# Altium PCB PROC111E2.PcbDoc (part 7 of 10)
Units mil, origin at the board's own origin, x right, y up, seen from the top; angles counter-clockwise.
Board outline 7700 x 2300 mil, 6 copper layers (Top Layer, GND 1, SIG 1, SIG 2, GND 2, Bottom Layer), stack 78.711 mil thick; 767 components, 596 nets, 2755 pads, 1578 vias.
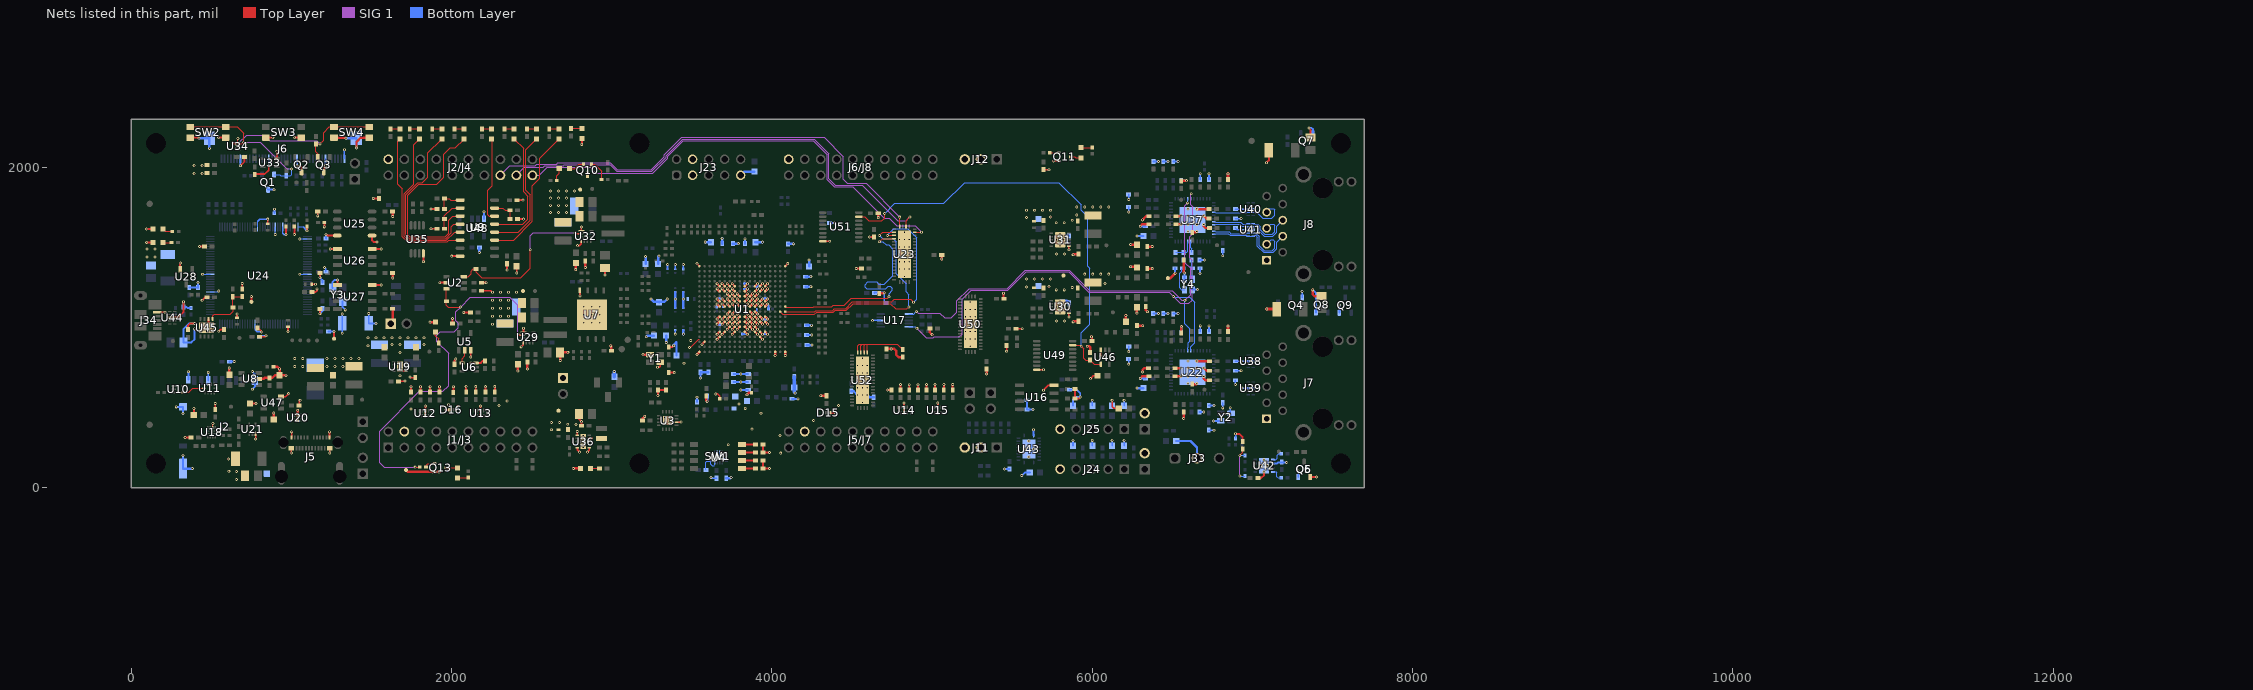
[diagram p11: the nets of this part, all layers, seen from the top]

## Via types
v1: diameter 18, hole 8, Top Layer to Bottom Layer, tented both sides, 1474 vias
v2: diameter 19.68, hole 7.87, Top Layer to Bottom Layer, tented both sides, 104 vias

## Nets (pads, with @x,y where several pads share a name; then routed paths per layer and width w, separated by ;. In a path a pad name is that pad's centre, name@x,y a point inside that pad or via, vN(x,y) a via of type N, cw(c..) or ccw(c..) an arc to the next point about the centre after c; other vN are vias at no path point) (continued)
ETH2_TD_B_P: J8.7 U37.4 U40.4 U40.7 | length 512.4
  Bottom Layer w4: U37.4@6759.03,1719.25 6766.12,1719.25 6770.11,1715.26 6951.17,1715.26 6961.96,1715.26 6965.96,1719.25 U40.7@6973.14,1719.25 U40.4@7006.02,1719.25 7013.2,1719.25 7017.19,1715.26 7031.41,1715.26 7065.94,1680.74 7120,1680.74 7140.49,1701.23 7140.49,1734.84 7132.92,1742.41 7101.74,1742.41 7089.08,1729.76 J8.7@7089.08,1720
ETH2_TD_C_N: J8.6 U37.8 U41.2 U41.9 | length 543.1
  Bottom Layer w4: U37.8@6759.03,1640.51 6766.12,1640.51 6770.11,1644.5 6922.46,1644.5 6933.69,1633.28 6961.69,1633.28 6965.69,1629.28 U41.9@6972.87,1629.28 U41.2@7005.75,1629.28 7012.93,1629.28 7016.92,1633.28 7030,1633.28 7038.3,1624.98 7038.3,1604.25 7073.24,1569.3 7127.85,1569.3 7152.19,1593.65 7152.19,1633.12 J8.6@7189.08,1670
ETH2_TD_C_P: J8.5 U37.7 U41.1 U41.10 | length 541.7
  Bottom Layer w4: U37.7@6759.03,1660.2 6766.12,1660.2 6770.11,1656.2 6927.31,1656.2 6938.54,1644.98 6961.69,1644.98 6965.69,1648.97 U41.10@6972.87,1648.97 U41.1@7005.75,1648.97 7012.93,1648.97 7016.92,1644.98 7034.85,1644.98 7050,1629.82 7050,1609.09 7078.09,1581 7123,1581 7140.49,1598.5 7140.49,1639.01 7134.5,1645 7114.08,1645 J8.5@7089.08,1620
ETH2_TD_D_N: J8.4 U37.11 U41.5 U41.6 | length 583.9
  Bottom Layer w4: U37.11@6759.03,1581.46 6766.12,1581.46 6770.11,1585.45 6850,1585.45 6861.23,1574.22 6961.69,1574.22 6965.69,1570.23 U41.6@6972.87,1570.23 U41.5@7005.75,1570.23 7012.93,1570.23 7016.92,1574.22 7020.52,1574.22 7031.57,1563.18 7031.57,1506.63 7070.15,1468.05 7129.73,1468.05 7152.19,1490.51 7152.19,1533.12 J8.4@7189.08,1570
ETH2_TD_D_P: J8.3 U37.10 U41.4 U41.7 | length 583.2
  Bottom Layer w4: U37.10@6759.03,1601.14 6766.12,1601.14 6770.11,1597.15 6854.85,1597.15 6866.07,1585.92 6961.69,1585.92 6965.69,1589.91 U41.7@6972.87,1589.91 U41.4@7005.75,1589.91 7012.93,1589.91 7016.92,1585.92 7025.37,1585.92 7043.27,1568.02 7043.27,1511.48 7075,1479.75 7124.88,1479.75 7140.49,1495.36 7140.49,1536.72 7129.83,1547.39 7116.46,1547.39 J8.3@7089.08,1520
ETH2_XI: R212.2 R213.2 U37.20 | length 139
  Bottom Layer w5.3: R213.2@6520,1468.62 R212.2@6570,1468.62 6588.54,1468.62 6595.65,1475.73 U37.20@6595.65,1536.18
ETH2_XO: R214.2 U37.19 | length 69.5
  Bottom Layer w5.3: U37.19@6615.33,1536.18 6615.33,1496.87 6620,1492.2 R214.2@6620,1468.62
ETH2_XTAL_XI: C189.1 R212.1 Y4.1 | length 219.5
  Bottom Layer w5.3: R212.1@6570,1421.38 6570,1375 C189.1@6565,1370 6557.39,1362.39 6557.39,1350 6545,1337.61 6545,1248.66 6557.24,1236.42 Y4.1@6576.38,1236.42
ETH2_XTAL_XO: C190.1 R214.1 Y4.3 | length 123.6
  Bottom Layer w5.3: R214.1@6620,1421.38 6620,1375 C190.1@6625,1370 6625,1301.78 Y4.3@6623.62,1300.4
FB_VDD_XDS3V3: C228.2 R251.1 R252.2 U45.5 | length 312.9
  Top Layer w5.3: U45.5@507.08,1053.44 507.08,1074.16 515.69,1082.78 617.61,1082.78 635.03,1100.19 C228.2@635.03,1124.76 631.97,1127.82 R251.1@631.97,1191.61 690.03,1191.61 R252.2@691.97,1193.54
GND: C1.2 C2.2 C3.2 C4.2 C5.2 C6.2 C7.2 C8.2 C9.2 C10.2 C11.2 C12.2 C13.2 C14.2 C15.2 C16.2 C17.2 C18.2 C19.1 C20.1 C21.1 C22.1 C23.2 C24.2 C25.2 C26.2 C27.2 C28.2 C29.1 C30.1 C31.1 C32.1 C33.2 C34.2 C35.2 C36.2 C37.2 C38.2 C39.1 C40.1 C41.1 C42.1 C43.1 C44.1 C45.1 C46.1 C47.1 C48.2 C49.2 C50.2 C51.2 C52.2 C53.2 C54.2 C55.2 C56.2 C57.1 C58.2 C59.2 C60.1 C61.1 C62.1 C63.2 C64.1 C65.1 C66.1 C67.2 C68.2 C69.2 C70.1 C71.1 C72.2 C73.2 C74.2 C75.2 C81.2 C82.2 C83.2 C84.2 C85.2 C86.2 C87.2 C88.2 C89.2 C90.2 C91.2 C92.2 C93.2 C94.2 C95.2 C96.2 C97.2 C98.2 C99.1 C100.1 C101.2 C102.2 C103.2 C104.2 C105.2 C106.2 C107.2 C108.2 C109.2 C110.2 C111.1 C112.2 C113.2 C114.2 C115.2 C116.2 C117.2 C118.2 C119.2 C120.2 C121.2 C122.2 C123.2 C124.2 C125.2 C126.2 C127.2 C128.2 C129.2 C130.2 C131.2 C132.2 C133.2 C136.1 C137.1 C138.1 C157.2 C158.2 C159.2 C160.2 C161.2 C162.2 C163.2 C164.2 C165.2 C166.2 C167.2 C168.2 C169.2 C170.2 C171.2 C172.2 C173.2 C174.2 C175.2 C176.2 C177.2 C178.2 C179.2 C180.2 C181.1 C182.1 C183.1 C184.1 C185.2 C186.2 C187.2 C188.2 C189.2 C190.2 C191.2 C192.2 C193.2 C194.2 C195.2 C196.2 C197.2 C198.2 C199.2 C200.2 C201.2 C202.2 C203.2 C204.2 C205.2 C206.2 C207.2 C208.2 C209.2 C210.2 C211.2 C212.2 C213.2 C214.2 C215.2 C216.2 C217.2 C218.2 C219.2 C220.2 C221.2 C222.2 C223.1 C224.2 C225.1 C226.1 C229.1 C234.2 C235.1 C236.2 C237.2 C238.1 C239.1 C240.1 C241.1 C242.1 C243.1 C244.1 C245.1 C246.1 C247.1 C248.2 C249.2 D1.1 D2.1 D4.1 D6.1 D15.1 D16.2 J1/J3.22 J2.6 J2.10 J2.S1 J2.S2 J2.S3 J2.S4 J2/J4.20 J5.A1 J5.A12 J5.B1 J5.B12 J5/J7.62 J6.7 J6.16 J6.25 J6.34 J6.40 J6.41 J6.42 J6/J8.60 J7.1 J8.1 J11.2 J11.3 J12.2 J12.3 J15.2 J16.2 J17.1 J18.1 J23.3 J23.4 J23.9 J24.5 J25.5 J33.2 Q1.3 Q2.3 Q3.3 Q4.2 Q5.2 Q6.2 Q7.2 Q8.2 Q9.2 Q10.3 Q11.2 Q13.2 R2.1 R6.1 R20.2 R21.1 R22.1 R23.1 R24.1 R25.1 R32.2 R39.1 R44.1 R95.1 R96.1 R97.1 R98.2 R107.1 R120.1 R121.1 R122.1 R123.1 R124.1 R125.1 R126.1 R127.1 R128.1 R148.1 R152.1 R154.1 R160.1 R161.1 R163.1 R202.1 R215.1 R216.1 R217.1 R218.1 R219.1 R220.1 R221.1 R222.1 R223.1 R250.1 R254.2 R255.2 R256.1 R274.1 R275.1 R276.1 R278.1 R289.1 R290.1 R293.1 R294.1 R299.2 R300.1 R304.1 R307.1 R316.2 R321.1 R322.1 R323.1 SW2.1 SW2.3 SW3.1 SW3.3 SW4.1 SW4.3 TP6.1 TP13.1 TP14.1 TP15.1 TP16.1 TP17.1 U1.A1 U1.A18 U1.E5 U1.E6 U1.E7 U1.E8 U1.E10 U1.E12 U1.E13 U1.E14 U1.F5 U1.F6 U1.F7 U1.F8 U1.F10 U1.F12 U1.F13 U1.F14 U1.G7 U1.G8 U1.G9 U1.G10 U1.G11 U1.G12 U1.H5 U1.H6 U1.H7 U1.H8 U1.H9 U1.H10 U1.H11 U1.H12 U1.H13 U1.H14 U1.J5 U1.J6 U1.J7 U1.J8 U1.J9 U1.J10 U1.J11 U1.J12 U1.J13 U1.J14 U1.K7 U1.K8 U1.K9 U1.K10 U1.K11 U1.K12 U1.L5 U1.L6 U1.L7 U1.L8 U1.L9 U1.L10 U1.L11 U1.L12 U1.L13 U1.L14 U1.M5 U1.M6 U1.M7 U1.M8 U1.M9 U1.M10 U1.M11 U1.M12 U1.M13 U1.M14 U1.N7 U1.N8 U1.N9 U1.N10 U1.N11 U1.N12 U1.P5 U1.P6 U1.P8 U1.P10 U1.P12 U1.P13 U1.P14 U1.R5 U1.R13 U1.T2 U1.V1 U1.V16 U1.V18 U2.2 U3.6 U3.17@3348.05,418.7 U4.10 U4.11 U5.3 U6.3 U7.4 U7.9 U8.2 U9.3 U12.3@1835,448.04 U12.8@1835,480.91 U13.3@2180,448.56 U13.8@2180,481.44 U14.3@4825,467.68 U14.8@4825,500.55 U15.3@5035.4,467.82 U15.8@5035.4,500.69 U16.4 U17.3 U18.10 U19.5 U19.9 U20.3@1038.54,453.43 U20.8@1038.54,420.56 U21.3 U22.49 U23.43 U25.5 U26.4 U27.4 U29.4 U29.7 U30.6 U30.11 U31.6 U31.11 U32.4 U32.7 U33.3 U34.2 U35.4 U36.1 U36.5 U36.6 U36.11@2821.22,287.66 U37.49 U38.3@7006.02,788.94 U38.8@6973.14,788.94 U39.3@7005.75,619.6 U39.8@6972.87,619.6 U40.3@7006.02,1738.94 U40.8@6973.14,1738.94 U41.3@7005.75,1609.6 U41.8@6972.87,1609.6 U42.2 U42.9 U43.11 U43.21 U46.3 U47.3 U48.16 U49.8 U50.43 U51.8 U52.43 Y1.2 Y1.4 Y2.2 Y2.4 Y4.2 Y4.4 | length 17319.2
  Top Layer w5.3: v1@3483.94,875.56 3492.6,875.56 3532.61,915.57 3532.61,916.37 3541.12,924.88 3544.78,924.88
  Top Layer w6: U34.2@665,2146.97 v1@665,2179.53
  Top Layer w7: U18.10@508.07,374.61 v1(508.07,400)
  Top Layer w8: v1(664.53,2180) v1@665,2179.53 ; v1@1000.24,347.64 v1(1000.43,347.83) ; v1@1236.46,347.64 v1(1236.65,347.83) ; U3.6@3403.17,408.86 v1(3432.52,408.86)
  Top Layer w10: v1(680,2009.61) 705.62,2035.22 C181.1@705.62,2065 ; C182.1@769.3,1958.19 832.83,1958.19 857.17,1982.52 v1(857.17,2009.61) ; v1(775,302.93) U21.3@774.98,335.87 ; U47.3@933.63,568.4 963.4,568.4 v1(981.5,586.5) ; v1(998.27,216.05) J5.B12@998.27,245.67 ; R299.2@1047.12,512.5 1047.12,538.62 v1(1053.5,545) ; v1(1238.42,216.05) J5.B1@1238.42,245.67 ; R98.2@1668.62,663.27 1703.78,663.27 1705.51,665 v1(1707.67,665) ; U19.9@1676.92,755.91 1676.92,742.13 1689.64,729.41 1699.16,729.41 1700.3,728.27 1707.67,728.27 1709.56,726.38 U19.5@1714.33,726.38 ; v1(1740,690.32) 1743.94,686.38 C109.2@1771.58,686.38 ; v1(2433.37,878.82) 2446.36,891.81 U29.7@2446.36,905.26 ; U29.4@2448.33,971.21 v1(2448.33,995.01) ; v1(2785.5,1511) 2797,1511 2808.03,1522.03 U32.7@2808.03,1537.88 ; U32.4@2810,1603.83 v1(2810,1627.63) ; v1(3531.39,1398.54) U1.A1@3547.13,1382.8 ; v1(3648.81,585) 3661.54,585 3674.25,572.29 R307.1@3674.25,555 ; U1.A18@4082.57,1382.8 v1(4098.31,1398.54) ; U51.8@4317.8,1538.35 v1(4360.59,1538.35) ; v1(5465.31,851.27) R289.1@5465.31,887.92 ; U49.8@5652.8,735.66 v1(5695.59,735.66) ; v1(5854.25,1065.8) U30.6@5854.25,1089.06 ; v1(5854.25,1484.99) U31.6@5854.25,1508.25 ; v1(6124.18,545) 6124.18,504.64 6134.15,494.67 C221.2@6165.63,494.67
  Top Layer w11: J5.A1@1000.24,312.6 v1@1000.24,347.64 ; J5.A12@1236.46,312.6 v1@1236.46,347.64
  Top Layer w12: v1(335,312.6) R95.1@372.78,312.6 ; SW2.1@367.32,2185.35 417,2185.35 420.21,2182.15 v1(421.83,2182.15) ; C101.2@389.29,454.11 v1(389.29,493.25) ; R97.1@523.29,487.03 v1(523.29,525) ; v1(544.55,2185.35) SW2.3@587.8,2185.35 ; C110.2@740,525.04 v1(777.78,525.04) ; SW3.1@839.76,2185.35 v1(883.01,2185.35) ; U33.3@907.66,2053.74 v1(907.66,2100) ; v1(1016.99,2185.35) SW3.3@1060.24,2185.35 ; v1(1034.33,2009.61) 1055,2009.61 1062.25,2002.35 Q2.3@1062.25,1969.78 ; Q3.3@1201.12,1969.78 1201.14,1999.25 v1(1211.5,2009.61) ; U25.5@1502.36,1573.86 1502.36,1543.52 1512.61,1533.27 v1(1533.19,1533.27) ; U27.4@1503.27,1265.27 v1(1560,1265.27) ; U26.4@1503.27,1490 v1(1560,1490) ; v1(1510,1806) R21.1@1545,1806 ; C72.2@1745,595.57 v1(1745,629.98) ; C73.2@1805,595.57 v1(1805,629.98) ; v1(1822.76,1410.12) U35.4@1822.76,1462.4 ; U12.3@1835,448.04 U12.8@1835,480.91 v1(1835,509.48) ; C74.2@1865,595.57 v1(1865,629.98) ; v1(1870,1616.57) R276.1@1907.31,1616.57 ; v1(1870,1739.85) R274.1@1907.31,1739.85 ; C75.2@1924,595.57 v1(1924,629.98) ; v1(1925,1279.45) U2.2@1967.11,1279.45 ; v1(1960,485.1) D16.2@1984.92,485.1 ; v1(2000.43,1445) U48.16@2052.72,1445 ; C97.2@2010,595 v1(2010,629.41) ; C64.1@2017.57,770.1 2017.57,795.11 v1(2025,802.54) ; v1(2075.37,1094.07) R20.2@2117.18,1094.07 ; C81.2@2090,596.09 v1(2090,630.5) ; v1(2118.71,815.97) U5.3@2118.71,857.27 ; v1(2120.87,777.98) U6.3@2152.96,777.98 2179.73,777.98 2191.61,789.85 2207.84,789.85 C63.2@2207.84,791.01 ; C82.2@2150,596.09 v1(2150,630.5) ; U13.3@2180,448.56 U13.8@2180,481.44 v1(2180,510) ; C57.1@2186.02,1279.45 v1(2215,1279.45) ; R6.1@2186.34,1229.13 2244.97,1229.13 2254.1,1220 v1(2255,1220) ; C83.2@2210,596.09 v1(2210,630.5) ; C84.2@2269,596.09 v1(2269,630.5) ; v1(2345.94,1358.33) C237.2@2345.94,1397.76 ; v1(2405.95,1339.91) C236.2@2405.95,1382.01 ; R278.1@2408.62,1795 v1(2445.32,1795) ; R275.1@2411.63,1676.55 v1(2448.33,1676.55) ; v1(2759.42,119.25) v1@2759.91,119.75 ; U36.5@2783.82,248.29 2784.2,248.29 2784.2,235.76 v1(2798.5,221.46) ; U36.1@2783.82,327.03 v1(2783.82,350) ; C185.2@2795,458.99 2795,426.59 v1(2810,411.59) 2810.69,410.9 2810.69,386.65 C186.2@2811.38,385.96 ; U7.4@2800,1232.08 2800,1197.93 v1(2800.41,1197.52) ; v1(2812.21,2143.35) 2812.72,2143.87 D4.1@2812.72,2180.75 ; Q10.3@2848,1943.6 v1(2848,1974.32) ; v1(2848.5,221.46) 2858.62,231.57 U36.6@2858.62,248.29 ; R160.1@2956.47,1370.85 2956.47,1328.5 v1(2956.79,1328.18) ; v1(3285,751.21) 3294.48,751.21 3301.99,758.72 Y1.2@3301.99,782.59 ; v1(3287.35,575.17) 3287.47,575.29 C48.2@3287.47,609.62 R2.1@3337.66,609.62 ; C58.2@3355,717.59 3389.33,717.59 v1(3389.46,717.47) ; R23.1@3943.62,169.51 R22.1@3943.62,119.51 v1(3984.6,119.51) ; R25.1@3943.62,269.51 R24.1@3943.62,219.51 v1(3984.6,219.51) ; D15.1@4364.37,466.66 v1(4395.17,466.66) ; v1(4526.3,1367.86) 4526.37,1367.93 R290.1@4558.11,1367.93 ; v1(4720.59,608.97) 4720.69,608.87 4747.01,608.87 C85.2@4747.11,608.78 ; C86.2@4802.11,607.56 v1@4802.11,641.97 ; C86.2@4802.11,608.78 v1(4802.11,643.18) ; U14.3@4825,467.68 U14.8@4825,500.55 v1(4825,527.91) ; C87.2@4857.11,607.56 v1(4857.11,641.97) ; C88.2@4911.11,607.56 v1(4911.11,641.97) ; C92.2@4965,609.62 v1(4965,644.03) ; C93.2@5017.97,608.92 v1(5017.97,643.32) ; v1(5035,527.91) 5035.4,527.5 U15.8@5035.4,500.69 U15.3@5035.4,467.82 ; C94.2@5073,608.92 v1(5073,643.32) ; C95.2@5128.54,608.92 v1(5128.54,643.32) ; v1@5339.88,709.09 v1(5340,708.97) ; R294.1@5525,992.02 5562.09,992.02 v1(5562.51,991.6) ; v1(5694.94,607.56) 5726.52,639.14 U16.4@5760.08,639.14 ; R304.1@5695.31,1985.02 v1(5730,1985) ; v1(5756.81,2039.68) Q11.2@5790.6,2039.68 ; R323.1@5892.56,615 R321.1@5892.56,556.99 5916.9,556.99 v1(5924.91,565) ; v1(5989.5,680.45) 6007.43,698.38 C248.2@6032.6,698.38 ; v1(6054.41,820.59) U46.3@6054.41,859.29 ; v1(6895,335.87) 6919.4,335.87 6940,315.27 C222.2@6940,288.62 ; C226.1@7033.62,60.4 7055.4,60.4 7072.8,77.8 v2(7072.8,99.05) ; v1(7087.71,2028.68) 7102.48,2043.44 C247.1@7102.48,2106.97 ; v1(7354.16,2245) 7364.16,2234.97 R255.2@7364.16,2186.97 ; Q5.2@7361.4,66.42 v1(7400,66.42)
  Top Layer w13: U1.P12@3893.59,973.35 v1(3909.34,957.6) ; U1.P13@3925.09,973.35 v1(3940.83,957.6) ; U1.P14@3956.58,973.35 v1(3972.33,957.6)
  Top Layer w15: v1(610.92,746.73) 611.03,746.63 C67.2@611.03,704.19 ; U8.2@795.16,678.6 823.99,678.6 830.8,685.41 C69.2@862.1,685.41 880.37,685.41 896.06,701.1 924.7,701.1 C68.2@924.76,701.16 ; R39.1@886.92,754.8 911.3,754.8 924.76,741.35 C68.2@924.76,701.16 ; C249.2@888.36,425.41 v1(888.36,465.6) ; v1(965,701.1) 964.95,701.16 C68.2@924.76,701.16 ; U20.8@1038.54,420.56 U20.3@1038.54,453.43 v1(1038.54,483.13) ; SW4.1@1264.76,2185.35 1335.13,2185.35 1339.19,2181.3 v1(1340,2181.3) ; v1(1405,2120.99) 1405,2158.4 1431.95,2185.35 SW4.3@1485.24,2185.35 ; J17.1@1618.62,1023.77 1631.5,1036.64 C136.1@1631.5,1117.23 ; v1(1631.5,1308.81) C137.1@1631.5,1340 ; v1(1631.5,1692.68) C138.1@1631.5,1723.86 ; TP13.1@1715,110 1727.2,97.8 Q13.2@1892.6,97.8 v1(1921.18,97.8) ; v1(1864.39,1033.2) D2.1@1898.27,1033.2 ; v1(2004.54,1055.56) 2004.54,1025.93 C65.1@2005.6,1024.86 ; C160.2@2412.84,770.19 2412.84,728.44 v1(2413.01,728.27) ; R154.1@2472.33,783.06 2472.33,741.32 v1(2472.51,741.14) ; v1(2677.33,794.21) R148.1@2677.33,844.68 2724.68,844.68 v1(2725,845) ; v1@2759.91,119.75 D6.1@2803.5,119.75 ; C177.2@2774.51,1402.8 2774.51,1361.06 v1(2774.69,1360.89) ; R163.1@2834,1415.68 2834,1373.93 v1(2834.18,1373.76) ; v1(2993.31,885.26) 2997.24,881.32 C66.1@2997.24,854.15 ; C60.1@3191.38,418.33 3191.38,431.06 v1(3205.32,445) ; v1(3195,830) 3195.16,829.84 Y1.4@3238.01,829.84 ; C59.2@3355,877.96 3377.36,877.96 3385.25,885.85 v1(3386.07,885.85) ; v1(3531.39,831.61) U1.V1@3547.13,847.36 ; v1(3562.88,894.61) U1.T2@3578.63,910.35 ; C91.2@3590,571.38 3590,543.54 v1(3595,538.54) ; v1(3657.37,926.1) U1.R5@3673.12,941.85 ; v1(3657.37,957.6) U1.P5@3673.12,973.35 ; v1(3657.37,1020.59) U1.M5@3673.12,1036.34 ; v1(3657.37,1052.09) U1.L5@3673.12,1067.83 ; v1(3657.37,1146.57) U1.J5@3673.12,1130.83 ; v1(3657.37,1178.07) U1.H5@3673.12,1162.32 ; v1(3657.37,1241.06) U1.F5@3673.12,1225.32 ; v1(3657.37,1272.56) U1.E5@3673.12,1256.81 ; v1(3688.87,957.6) U1.P6@3704.61,973.35 ; v1(3688.87,1020.59) U1.M6@3704.61,1036.34 ; v1(3688.87,1052.09) U1.L6@3704.61,1067.83 ; v1(3688.87,1146.57) U1.J6@3704.61,1130.83 ; v1(3688.87,1178.07) U1.H6@3704.61,1162.32 ; v1(3688.87,1241.06) U1.F6@3704.61,1225.32 ; v1(3688.87,1272.56) U1.E6@3704.61,1256.81 ; v1(3720.36,989.09) U1.N7@3736.11,1004.84 ; v1(3720.36,1020.59) U1.M7@3736.11,1036.34 ; v1(3720.36,1052.09) U1.L7@3736.11,1067.83 ; v1(3720.36,1083.58) U1.K7@3736.11,1099.33 ; v1(3720.36,1146.57) U1.J7@3736.11,1130.83 ; v1(3720.36,1178.07) U1.H7@3736.11,1162.32 ; v1(3720.36,1209.57) U1.G7@3736.11,1193.82 ; v1(3720.36,1241.06) U1.F7@3736.11,1225.32 ; v1(3720.36,1272.56) U1.E7@3736.11,1256.81 ; v1(3751.86,957.6) U1.P8@3767.61,973.35 ; v1(3751.86,989.09) U1.N8@3767.61,1004.84 ; v1(3751.86,1020.59) U1.M8@3767.61,1036.34 ; v1(3751.86,1052.09) U1.L8@3767.61,1067.83 ; v1(3751.86,1083.58) U1.K8@3767.61,1099.33 ; v1(3751.86,1146.57) U1.J8@3767.61,1130.83 ; v1(3751.86,1178.07) U1.H8@3767.61,1162.32 ; v1(3751.86,1209.57) U1.G8@3767.61,1193.82 ; v1(3751.86,1241.06) U1.F8@3767.61,1225.32 ; v1(3751.86,1272.56) U1.E8@3767.61,1256.81 ; v1(3783.35,989.09) U1.N9@3799.1,1004.84 ; v1(3783.35,1020.59) U1.M9@3799.1,1036.34 ; v1(3783.35,1052.09) U1.L9@3799.1,1067.83 ; v1(3783.35,1083.58) U1.K9@3799.1,1099.33 ; v1(3783.35,1146.57) U1.J9@3799.1,1130.83 ; v1(3783.35,1178.07) U1.H9@3799.1,1162.32 ; v1(3783.35,1209.57) U1.G9@3799.1,1193.82 ; U1.P10@3830.6,973.35 v1(3846.35,957.6) ; U1.N10@3830.6,1004.84 v1(3846.35,989.09) ; U1.M10@3830.6,1036.34 v1(3846.35,1020.59) ; U1.L10@3830.6,1067.83 v1(3846.35,1052.09) ; U1.K10@3830.6,1099.33 v1(3846.35,1083.58) ; U1.J10@3830.6,1130.83 v1(3846.35,1146.57) ; U1.H10@3830.6,1162.32 v1(3846.35,1178.07) ; U1.G10@3830.6,1193.82 v1(3846.35,1209.57) ; U1.F10@3830.6,1225.32 v1(3846.35,1241.06) ; U1.E10@3830.6,1256.81 v1(3846.35,1272.56) ; v1(3843.32,579.5) 3855.66,591.83 R44.1@3872.63,591.83 ; U1.N11@3862.09,1004.84 v1(3877.84,989.09) ; U1.M11@3862.09,1036.34 v1(3877.84,1020.59) ; U1.L11@3862.09,1067.83 v1(3877.84,1052.09) ; U1.K11@3862.09,1099.33 v1(3877.84,1083.58) ; U1.J11@3862.09,1130.83 v1(3877.84,1146.57) ; U1.H11@3862.09,1162.32 v1(3877.84,1178.07) ; U1.G11@3862.09,1193.82 v1(3877.84,1209.57) ; U1.N12@3893.59,1004.84 v1(3909.34,989.09) ; U1.M12@3893.59,1036.34 v1(3909.34,1020.59) ; U1.L12@3893.59,1067.83 v1(3909.34,1052.09) ; U1.K12@3893.59,1099.33 v1(3909.34,1083.58) ; U1.J12@3893.59,1130.83 v1(3909.34,1146.57) ; U1.H12@3893.59,1162.32 v1(3909.34,1178.07) ; U1.G12@3893.59,1193.82 v1(3909.34,1209.57) ; U1.F12@3893.59,1225.32 v1(3909.34,1241.06) ; U1.E12@3893.59,1256.81 v1(3909.34,1272.56) ; U1.R13@3925.09,941.85 v1(3940.83,926.1) ; U1.M13@3925.09,1036.34 v1(3940.83,1020.59) ; U1.L13@3925.09,1067.83 v1(3940.83,1052.09) ; U1.J13@3925.09,1130.83 v1(3940.83,1146.57) ; U1.H13@3925.09,1162.32 v1(3940.83,1178.07) ; U1.F13@3925.09,1225.32 v1(3940.83,1241.06) ; U1.E13@3925.09,1256.81 v1(3940.83,1272.56) ; U1.M14@3956.58,1036.34 v1(3972.33,1020.59) ; U1.L14@3956.58,1067.83 v1(3972.33,1052.09) ; U1.J14@3956.58,1130.83 v1(3972.33,1146.57) ; U1.H14@3956.58,1162.32 v1(3972.33,1178.07) ; U1.F14@3956.58,1225.32 v1(3972.33,1241.06) ; U1.E14@3956.58,1256.81 v1(3972.33,1272.56) ; v1(4019.57,825) U1.V16@4019.57,847.36 ; v1(4082.57,825) U1.V18@4082.57,847.36 ; v1(4305.32,573.56) C96.2@4339.72,573.56 ; v1(4610,1564.77) C241.1@4636.65,1564.77 ; v1(4663.62,1685.42) C246.1@4663.62,1712.48 ; C240.1@4670.38,1213.22 4697.36,1213.22 v1(4701.07,1216.93) ; C245.1@4715,864.8 4716.1,865.9 v1(4745,865.9) 4763.67,865.9 4776.02,853.55 4776.02,828.46 4790.08,814.4 R256.1@4816.77,814.4 ; C111.1@4985.38,992.82 4985.38,969.7 v1(5000,955.08) ; v1(5060,1426.95) C242.1@5060,1451.95 ; v1@5339.88,709.09 C239.1@5339.88,741.15 ; C238.1@5445.86,1179.87 v1(5445.86,1213.79) ; v1(5880.69,1035) 5881.5,1035 5885.23,1038.74 R152.1@5914.13,1038.74 ; v1(5880.69,1454.19) 5881.5,1454.19 5885.23,1457.92 R161.1@5914.13,1457.92 ; v1(5968.5,882.8) 5981.65,882.8 5986.5,877.96 R96.1@5986.5,843.62 ; v1(5994.69,941.85) 5998.62,937.91 C43.1@5998.62,914.8 ; C122.2@6210,1035.15 v1(6210,1075.06) ; v1(6240,1379.35) 6240.74,1378.61 C114.2@6279,1378.61 ; v1(6240,1517.45) 6240.74,1516.71 C191.2@6279,1516.71 ; v1(6278.93,1089.06) C199.2@6278.93,1125.48 ; C123.2@6280.09,1010.77 v1(6315,1010.77) ; v1(6300,682.33) 6312.71,695.04 C133.2@6355.51,695.04 ; v1(6300,1632.33) 6312.71,1645.04 C210.2@6355.51,1645.04 ; v1(6313.62,721.81) 6313.62,735 6323.66,745.04 C119.2@6350.51,745.04 ; v1(6313.62,1671.81) 6336.85,1695.04 C196.2@6355.51,1695.04 ; C200.2@6334,1131.36 6334,1108.26 v1(6344,1098.26) ; C115.2@6344,1366.9 6374.83,1366.9 v1(6375,1367.07) ; C192.2@6344,1505 6374.83,1505 v1(6375,1505.17) ; TP16.1@6471.65,1308.13 6488.28,1308.13 v1(6517.76,1337.61) ; C132.2@6517.56,695.04 6551.07,695.04 6553.04,693.07 v2(6554.31,693.07) ; C118.2@6517.56,745.04 6552.34,745.04 v2(6554.31,747.01) ; C209.2@6522.56,1645.04 6552.34,1645.04 v2(6554.31,1643.07) ; C195.2@6522.56,1695.04 6552.34,1695.04 v2(6554.31,1697.01) ; C116.2@6556.28,968.7 v1(6556.28,1005) ; C193.2@6556.28,1915.34 6586.92,1915.34 v1(6588.38,1916.8) ; v1(6570.85,431.38) R126.1@6570.85,471.38 ; R221.1@6570.97,1421.26 6570.97,1343.94 v1(6575,1339.91) ; C130.2@6625,644.09 6647.07,644.09 v2(6652.14,649.17) ; C207.2@6625,1594.09 6647.07,1594.09 v2(6652.14,1599.17) ; v2(6652.14,790.91) 6654.11,788.94 C126.2@6731.79,788.94 ; v2(6652.14,1740.91) 6654.11,1738.94 C203.2@6727.79,1738.94 ; v2(6696.04,693.07) 6696.04,680.77 6705.98,670.83 C124.2@6731.79,670.83 ; v2(6696.04,747.01) 6713.17,729.88 C120.2@6731.79,729.88 ; v2(6696.04,1643.07) 6696.04,1630.77 6705.98,1620.83 C201.2@6731.79,1620.83 ; v2(6696.04,1697.01) 6713.17,1679.88 C197.2@6727.79,1679.88 ; v1(7377.27,1235) 7377.27,1206.56 7388.83,1195 R254.2@7430.57,1195
  Top Layer w20: R123.1@6848,973.31 v1(6848,1009.61) ; R218.1@6848,1923.31 v1(6848,1959.61) ; v1(7090,1115) C235.1@7152.32,1115
  Bottom Layer w7: v1@3658.2,198.58 U4.10@3658.2,219.28 ; 3673.95,202.09 U4.11@3673.95,219.28
  Bottom Layer w8: v1@3658.2,198.58 v1@3664.32,192.46 ; v1(3664.32,192.41) v1@3664.32,192.46 ; 3673.95,202.09 v1@3664.32,192.46 ; v1(4627.36,1042.24) 4628.87,1043.75 U17.3@4680.08,1043.75 ; R250.1@6895,307.24 v1(6895,335.87) ; v1(6930,1609.6) U41.8@6972.87,1609.6 U41.3@7005.75,1609.6
  Bottom Layer w10: J6.7@679.88,2053.35 679.88,2009.73 v1(680,2009.61) ; J6.16@857.05,2053.35 857.05,2009.73 v1(857.17,2009.61) ; J6.25@1034.21,2053.35 1034.21,2009.73 v1(1034.33,2009.61) ; J6.34@1211.38,2053.35 1211.38,2009.73 v1(1211.5,2009.61) ; J6.40@1329.49,2053.35 1329.49,2109.49 v1(1330,2110) ; C211.2@5880,261.5 v1(5880,295) ; C216.2@6000,261.5 v1(6000,295) ; C219.2@6000,511.5 v1(6000,545) ; C215.2@6124.18,261.5 v1(6124.18,295) ; C218.2@6124.18,511.5 v1(6124.18,545) ; C214.2@6199.18,261.5 v1(6199.18,295) ; C217.2@6199.18,511.5 v1(6199.18,545) ; v1(6893.84,643.12) C125.2@6893.84,670.83 ; C121.2@6893.84,729.88 v1(6930,729.88) ; C127.2@6893.84,788.94 v1(6930,788.94) U38.8@6973.14,788.94 U38.3@7006.02,788.94 ; C202.2@6893.84,1620.83 6905.06,1609.6 v1(6930,1609.6) ; C198.2@6893.84,1679.88 v1(6930,1679.88) ; C204.2@6893.84,1738.94 v1(6930,1738.94) U40.8@6973.14,1738.94 U40.3@7006.02,1738.94 ; v1(6935,621.55) 6937.16,621.55 6939.12,619.6 U39.8@6972.87,619.6 U39.3@7005.75,619.6
  Bottom Layer w12: v1(279.76,504.25) J2.S2@321.97,504.25 v1(321.97,462.05) ; J2.10@355.43,673.54 v1(355.43,723.39) ; J2.6@479.45,669.61 v1(479.45,719.45) ; C71.1@611.42,785.43 612.83,786.84 v1(641.79,786.84) ; v1(755,614.21) 770.79,630 J2.S1@770.79,669.61 770.79,709.21 v1(755,725) ; Q1.3@852.98,1860.51 889.49,1860.51 v1(890,1860) ; v1(1481.54,1086.51) C234.2@1481.54,1025 v1(1527.39,1025) ; U9.3@2201.37,1678.43 v1@2201.37,1722.46 ; C42.1@3348.24,1365.28 v1(3348.24,1393.66) ; v1(3395.84,958.19) C45.1@3395.84,981.57 ; C21.1@3395.84,1365.28 3395.84,1393.26 v1(3396.24,1393.66) ; C49.2@3445.84,1365.28 3445.84,1393.26 v1(3446.24,1393.66) ; v1(3446.24,1177.95) v1@3446.46,1177.95 ; C38.2@3531.39,533.27 v1(3531.39,564.07) ; v1(3618.83,62.84) 3623.32,58.35 C61.1@3653.69,58.35 ; C54.2@3654.78,1128.1 3654.78,1143.99 v1(3657.37,1146.57) ; v1(3657.37,1020.59) 3660.59,1017.37 C56.2@3673,1017.37 3685.64,1017.37 v1(3688.87,1020.59) ; v1(3657.37,1178.07) 3659.37,1180.07 3686.86,1180.07 v1(3688.87,1178.07) ; v1(3688.87,1146.57) 3693.17,1142.27 C46.1@3693.17,1128.1 ; C34.2@3760,658.97 v1(3805.01,658.97) C27.2@3851.69,658.97 ; C36.2@3760,708.97 v1(3805.01,708.97) C28.2@3851.69,708.97 ; v1(3805.01,608.97) C26.2@3851.69,608.97 ; C50.2@3814.85,959.09 3844.85,959.09 v1(3846.35,957.6) ; C22.1@3904.97,1115.08 3904.97,1087.95 v1(3909.34,1083.58) ; v1(3909.34,1241.06) 3905.95,1244.45 C51.2@3905.95,1257.37 3905.95,1269.18 v1(3909.34,1272.56) ; v1(3940.83,957.6) 3943.24,960.01 3969.92,960.01 v1(3972.33,957.6) ; v1(3940.83,1052.09) 3944.25,1048.67 C47.1@3956.58,1048.67 ; v1(3940.83,1178.07) 3942.84,1180.07 3970.33,1180.07 v1(3972.33,1178.07) ; C47.1@3956.58,1047.9 C47.1@3956.58,1048.67 ; v1(3972.33,1052.09) 3968.91,1048.67 C47.1@3956.58,1048.67 ; v1(3972.33,1146.57) 3977.01,1141.9 C55.2@3977.01,1115.08 ; C24.2@4124.58,554.26 v1(4162.56,554.26) ; R300.1@4362.13,1652.52 v1(4389.19,1652.52) ; R293.1@4638.88,1215.33 4640.48,1216.93 v1(4701.07,1216.93) 4701.07,1162.37 C100.1@4711.38,1152.06 ; v1(5452.83,116.42) C223.1@5483.66,116.42 ; v1(5560,75) 5578.47,93.47 C224.2@5610.55,93.47 ; R316.2@5593.62,545.04 C99.1@5593.62,487.03 v1(5630,487.03) ; U43.11@5633.19,325.27 v1(5633.19,361.28) ; R322.1@5858.93,611.02 5903.98,611.02 5924.91,590.09 v1(5924.91,565) 5895.93,565 5880,549.07 C212.2@5880,511.5 ; v1(6227.6,770.73) 6227.68,770.81 R120.1@6227.68,802.65 ; v1(6227.6,1720.73) 6227.68,1720.81 R215.1@6227.68,1752.65 ; v1(6227.68,849.04) 6227.76,849.12 R121.1@6227.76,880.96 ; v1(6227.68,1799.04) 6227.76,1799.12 R216.1@6227.76,1830.96 ; v1(6280,1571.55) v1@6280.31,1571.24 ; v1(6300,1632.33) v1@6300.37,1631.97 ; R127.1@6383.01,1086.59 6413.24,1086.59 v1(6413.32,1086.51) ; R222.1@6383.01,2036.59 6413.24,2036.59 v1(6413.32,2036.51) ; R128.1@6443.01,1086.59 6473.24,1086.59 v1(6473.32,1086.51) ; R223.1@6443.01,2036.59 6473.24,2036.59 v1(6473.32,2036.51) ; R125.1@6506.28,1086.67 6536.51,1086.67 v1(6536.59,1086.59) ; R217.1@6506.28,2036.67 6536.51,2036.67 v1(6536.59,2036.59) ; v1(6517.76,1337.61) C189.2@6517.76,1370 ; C117.2@6556.28,968.7 v1(6556.28,1005) ; C194.2@6556.28,1918.7 6584.85,1918.7 6586.75,1916.8 v1(6588.38,1916.8) ; v1(6575,1339.91) 6575,1301.78 Y4.2@6576.38,1300.4 ; Y4.4@6623.62,1236.42 6623.81,1236.24 v1(6658.19,1236.24) ; C131.2@6670,471.38 v1(6696.04,471.38) ; C208.2@6670,1421.38 v1(6701.84,1421.38) ; v1(6672.24,1337.61) C190.2@6672.24,1370 ; R124.1@6674.39,973.7 v1(6674.39,1010) ; R219.1@6674.39,1923.7 v1(6674.39,1960) ; C112.2@6728.01,358.25 v1(6760.4,358.25) ; C113.2@6728.01,512.74 v1(6760.4,512.74) ; R122.1@6729.39,973.7 v1(6729.39,1010) ; R220.1@6729.39,1923.7 v1(6729.39,1960) ; v1(6758.1,415.5) 6796.23,415.5 Y2.2@6797.61,416.88 ; v1(6815,497.91) R107.1@6815,529.75 ; v1(6815,1447.91) R202.1@6815,1479.75 ; Y2.4@6861.59,464.12 6861.77,464.31 v1(6861.77,498.69) ; U42.2@7127.91,149.25 7153.38,149.25 7160.27,156.14 v1(7213.78,156.14) ; v1(7285,105) 7285,103.38 7286.6,101.78 Q6.2@7286.6,66.42 ; v1(7310.69,1224.19) 7311.5,1223.38 Q4.2@7311.5,1187.24 ; v1(7354.16,2245) 7370.37,2245 7377.4,2237.97 Q7.2@7377.4,2212.24 ; v1(7377.27,1235) 7396.47,1215.8 Q8.2@7396.47,1093.42 ; Q9.2@7542.92,1092.15 v1(7542.92,1140)
  Bottom Layer w15: v1(321.97,201.12) J2.S3@321.97,118.43 378.36,118.43 379.19,119.25 v1(380,119.25) ; v1(421.83,2182.15) 486.12,2182.15 J6.42@486.97,2181.3 486.97,2118.74 v1(486.83,2118.6) ; v1(1340,2181.3) J6.41@1404.29,2181.3 1405.14,2180.45 1405.14,2121.13 v1(1405,2120.99) ; v1(2172.21,1467.82) C70.1@2172.21,1499.2 ; C53.2@3210,1396.25 3210.5,1396.75 v1@3210.5,1435.42 ; v1(3215,941.85) 3222.44,949.29 C2.2@3262.14,949.29 ; v1(3243.98,1177.95) 3262.59,1159.34 3293.76,1159.34 C52.2@3295,1158.1 3296.24,1159.34 3327.41,1159.34 v1(3346.02,1177.95) ; C3.2@3288.51,1396.25 3288.51,1442.01 3291.5,1445 v1(3294.5,1445) ; C1.2@3338.57,949.29 3338.57,907.5 v1(3339.76,906.31) ; v1(3386.07,885.85) 3386.07,891.01 3403.5,908.44 C14.2@3403.5,824.72 ; C40.1@3396.24,1122.3 v1(3396.24,1177.95) C44.1@3396.24,1221.06 ; C20.1@3445.84,981.57 3445.84,959.97 3446.81,959 v1(3446.81,958.19) ; v1(3446.24,1177.95) C32.1@3446.24,1221.33 ; C29.1@3446.46,1121.9 v1@3446.46,1177.95 ; v1(3553.63,684.41) C15.2@3553.63,720.13 C7.2@3603.63,720.13 ; v1(3583.43,1532.95) 3585.05,1532.95 3586.44,1531.55 C6.2@3619.13,1531.55 ; v1(3595,538.54) C90.2@3595,571.29 ; C16.2@3688.87,1523.53 v1(3688.87,1556.28) ; C62.1@3713.69,58.35 3740.38,58.35 v1(3744.87,62.84) ; C10.2@3756.08,1523.53 v1(3790,1523.53) ; J23.9@3804.17,1950 3827.68,1973.5 C213.2@3890,1973.5 ; C31.1@3827.84,1239.57 3844.04,1239.57 3845.53,1241.06 v1(3846.35,1241.06) ; C30.1@3827.99,1273.75 3829.18,1272.56 v1(3846.35,1272.56) ; C11.2@3831.66,1523.53 v1(3831.66,1553.28) ; C5.2@3896.57,1532.99 3940.63,1532.99 v1(3940.74,1532.88) ; C12.2@4100.67,1521.84 v1(4133.42,1521.84) ; C18.2@4209.8,1254.06 v1(4242.55,1254.06) ; C13.2@4209.8,1317.07 v1(4242.55,1317.07) ; C17.2@4214.47,1013.32 v1(4247.22,1013.32) ; C8.2@4215.8,952.97 v1(4248.55,952.97) ; C9.2@4217.29,890 v1(4250.04,890) ; C4.2@4231.5,1381.81 v1(4231.5,1421.38) ; C243.1@4495.23,601.69 4510.67,601.69 v2(4534.49,577.87) ; v2(4595.51,577.87) 4609.31,564.07 C244.1@4635,564.07 ; v2(5799.13,1165.84) 5840.47,1165.84 5846,1160.3 5849.93,1160.3 5854.25,1155.99 C166.2@5854.25,1152.06 ; v2(5799.13,1585.02) 5812.76,1571.39 5854.25,1571.39 C178.2@5854.25,1571.24 ; v1(6280,621.55) 6280.31,621.24 C128.2@6319.86,621.24 ; v1@6280.31,1571.24 C205.2@6319.86,1571.24 ; v1(6300,682.33) 6300.37,681.97 C129.2@6331.89,681.97 ; v1@6300.37,1631.97 C206.2@6331.89,1631.97 ; C220.2@6523.66,290.82 6614.35,290.82 6654.17,250.99 J33.2@6654.17,183.86
  Bottom Layer w20: C89.2@3015,691.5 v1(3015,725) ; C35.2@4139.44,693.51 C23.2@4139.44,624.92 4139.44,596.22 v1(4144.81,590.85)
  other v1: 655,50.5 655,100.5 608.25,102 605,178.5 4055,215 3726.88,267.57 4050,325.27 2622.18,361.28 3875,364.8 2775.94,394.13 2724.68,395.61 2622.18,406.28 2672.19,406.28 4260,418.7 3931.68,464.25 1745.98,490.87 3832.75,495 2035,507.3 2295,512.52 4415,512.52 1980,517.53 3793.42,521.68 2345.94,540.24 1677.39,698.66 924.81,741.4 1019.88,756.7 1069.88,756.7 1219.88,756.7 1269.88,756.7 1319.88,756.7 3450,776.33 1019.88,806.7 1069.88,806.7 1219.88,806.7 1269.88,806.7 1319.88,806.7 1369.88,806.7 1419.88,806.7 1677.39,843.3 3484.5,875.36 1477.39,885.51 1627.39,893.3 1677.39,893.3 1827.39,893.3 3492.53,918.09 1477.39,935.51 1527.39,935.51 1577.39,935.51 1627.39,935.51 1677.39,935.51 1727.39,935.51 1777.39,935.51 1827.39,935.51 2255,1020 2825,1029.5 2875,1029.5 2925,1029.5 5777.2,1040 5827.2,1040 2255,1070 2305,1070 2355,1070 2825,1079.5 2875,1079.5 2925,1079.5 2255,1120 2305,1120 2355,1120 2825,1129.5 2875,1129.5 2925,1129.5 2255,1170 2305,1170 2355,1170 2305,1220 2355,1220 2405,1220 5775,1235 5825,1235 5875,1250 5590,1252.62 5730,1255 6080,1275 5590,1302.62 5640,1302.62 5690,1302.62 5740,1302.62 5953.33,1332.62 6003.33,1332.62 6053.33,1332.62 6103.33,1332.62 3210.5,1442.5 5777.2,1459.19 5827.2,1459.19 5775,1654.19 5825,1654.19 5875,1669.19 5590,1686.81 5740,1690 5903.33,1701.81 2616.67,1717.62 2666.67,1717.62 2716.67,1717.62 2201.31,1722.52 5590,1731.81 5640,1731.81 5690,1731.81 5740,1731.81 5903.33,1751.81 5953.33,1751.81 6003.33,1751.81 6053.33,1751.81 6103.33,1751.81 2616.67,1762.62 2666.67,1762.62 2716.67,1762.62 2616.67,1807.62 2666.67,1807.62 2716.67,1807.62 2616.67,1852.62 2666.67,1852.62 2716.67,1852.62 2766.67,1852.62 391.4,1960.39 441.4,1960.39 391.4,2010.39 441.4,2010.39
  other v2: 7050.16,136.46 7095.43,136.46 7072.8,173.86 5603.66,190.43 5573.15,240.62 5634.17,240.62 2821.22,250.25 2821.22,287.66 5603.66,290.82 2821.22,325.06 3329.35,400 3366.75,400 3329.35,437.4 3366.75,437.4 4565,531.81 4565,577.87 4534.49,623.94 4565,623.94 4595.51,623.94 6598.21,649.17 4534.49,670 4565,670 4595.51,670 6598.21,693.07 6652.14,693.07 4534.49,716.06 4565,716.06 4595.51,716.06 1676.92,734.25 6598.21,747.01 6652.14,747.01 4534.49,762.13 4565,762.13 4595.51,762.13 1676.92,777.56 6598.21,790.91 4565,808.19 5238.39,881.85 5207.87,927.91 5238.39,927.91 5268.9,927.91 5207.87,973.97 5238.39,973.97 5268.9,973.97 5207.87,1020.04 5238.39,1020.04 5268.9,1020.04 5207.87,1066.1 5238.39,1066.1 5268.9,1066.1 5799.13,1091.03 5207.87,1112.16 5238.39,1112.16 5268.9,1112.16 5776.49,1128.43 5821.77,1128.43 5238.39,1158.22 4827.2,1318.31 4796.69,1364.37 4827.2,1364.37 4857.72,1364.37 4796.69,1410.44 4827.2,1410.44 4857.72,1410.44 4796.69,1456.5 4827.2,1456.5 4857.72,1456.5 4796.69,1502.56 4827.2,1502.56 4857.72,1502.56 5799.13,1510.22 5776.49,1547.62 5821.77,1547.62 4796.69,1548.62 4827.2,1548.62 4857.72,1548.62 4827.2,1594.69 6598.21,1599.17 6598.21,1643.07 6652.14,1643.07 6598.21,1697.01 6652.14,1697.01 6598.21,1740.91
GND_XDS: C134.1 C135.1 C139.1 C140.1 C141.1 C142.2 C143.1 C144.1 C145.1 C146.2 C147.1 C148.2 C149.2 C150.1 C151.1 C152.1 C153.1 C154.1 C155.1 C156.2 C227.2 C230.1 C231.2 C232.2 C233.1 C234.1 D3.1 DS3.1 J34.5 R137.1 R145.1 R252.1 R253.2 R261.2 R308.2 R309.2 R310.2 TP24.1 TP26.1 U24.10 U24.17 U24.48 U24.55 U24.58 U24.64 U24.66 U24.80 U24.114 U25.4 U26.5 U27.5 U28.2 U44.3@271.44,1060.81 U44.8@238.56,1060.81 U45.6 U45.9@468.69,998.32 Y3.2 Y3.4 | length 2831
  Top Layer w8: J34.5@161.81,1095.26 208.68,1095.26 v1(208.94,1095) v1@210,1095
  Top Layer w12: v1(95,1531.39) D3.1@133.5,1531.39 ; v1(95,1614.41) DS3.1@133.5,1614.41 ; U44.8@238.56,1060.81 U44.3@271.44,1060.81 286.77,1060.81 325,1099.04 v1(325,1160.27) ; U28.2@304.1,1363.89 304.1,1401.9 v1(305,1402.8) ; C231.2@352.83,985.89 352.83,1011.2 366.63,1025 v1(395,1025) ; v1(424.55,1505.66) C150.1@456.88,1505.66 ; v1(441.26,1170) 459.73,1188.47 C145.1@471.69,1188.47 ; U45.9@468.69,998.32 481.48,1011.12 U45.6@481.48,1053.44 ; v1(545,976.17) 554.72,985.89 C233.1@577.56,985.89 ; C232.2@660,1060.15 660,1083.82 v1(660.2,1084.01) ; R252.1@691.97,1240.79 v1(691.97,1274.26) ; TP24.1@748.48,1160.35 v1(748.48,1193.83) ; C147.1@787.63,997.6 v1(813.07,972.16) ; C155.1@798.6,941.85 798.79,942.03 834.53,942.03 v1(840.5,948) ; C148.2@850.81,1647.63 v1(850.81,1676.55) ; v1(965,1579.87) R261.2@965,1630.31 ; v1(977.49,974.51) C146.2@977.49,1005.32 ; v1(1016.99,1579.87) R308.2@1016.99,1630.31 ; v1(1095.89,1603.83) R309.2@1095.89,1630.31 ; C156.2@1125,1270 v1(1149.04,1270) ; C153.1@1128.62,1221.57 1150.33,1221.57 1158.9,1230.14 v1(1158.9,1240.98) ; v1(1163.31,1697.01) C141.1@1163.31,1723.86 ; v1(1176.17,1085.27) C139.1@1176.17,1115.27 ; v1(1176.17,1312.74) C140.1@1176.17,1340 ; v1(1204,1628.35) 1204.28,1628.63 R310.2@1204.28,1656.39 ; v1(1215.02,1581.46) 1222.61,1573.86 U25.4@1285.36,1573.86 ; v1(1241.37,1490) U26.5@1286.73,1490 ; TP26.1@1265,929.89 v1(1265,974.22) ; U27.5@1286.73,1265.27 v1(1286.73,1296.18)
  Bottom Layer w7: v1@444.89,1332.24 U24.17@492.35,1332.24 ; U24.10@492.35,1222.01 v1@539.81,1222.01 ; 771.88,986.47 U24.114@771.88,1021.22 ; U24.48@787.63,1627.52 787.63,1661.88 ; v1@897.86,1580.06 U24.55@897.86,1627.52 ; 945.11,1589.53 U24.58@945.11,1627.52 ; U24.64@1039.59,1627.52 1072.2,1627.52 ; v1@1051.19,1332.24 U24.80@1098.65,1332.24 ; v1@1051.19,1552.72 U24.66@1098.65,1552.72
  Bottom Layer w8: v1(444.7,1332.06) v1@444.89,1332.24 ; v1@539.81,1222.01 545,1227.2 v1(545,1228.07) ; 771.88,986.47 786.19,972.16 v1(813.07,972.16) ; 787.63,1661.88 802.3,1676.55 v1(850.81,1676.55) ; v1@897.86,1580.06 v1(898.05,1579.87) ; 945.11,1589.53 954.76,1579.87 v1(965,1579.87) ; v1(1051,1332.06) v1@1051.19,1332.24 ; v1(1051,1552.53) v1@1051.19,1552.72 ; 1072.2,1627.52 v1(1095.89,1603.83)
  Bottom Layer w10: v1(1206,1374.46) 1212.81,1367.65 C149.2@1212.81,1347.99
  Bottom Layer w12: v1(325,1160.27) C135.1@325,1129 343.2,1129 351.14,1121.06 R137.1@371.47,1121.06 ; C151.1@360.82,1249.29 411.88,1249.29 C152.1@415.82,1245.35 ; v1(393.98,991.38) 393.98,926.52 374.15,906.68 C227.2@325,906.68 326.08,907.77 326.08,990.53 360.55,1025 v1(395,1025) ; C152.1@415.82,1249.29 v1(415.82,1280) ; C154.1@798.6,941.85 804.75,948 v1(840.5,948) ; R145.1@892.1,1713.62 892.38,1713.9 892.38,1737.58 v1(892.66,1737.87) ; v1(1176.17,1085.27) 1192.83,1101.93 1192.83,1117.59 C143.1@1192.72,1117.71 ; v1(1176.17,1312.74) 1192.72,1296.18 C144.1@1192.72,1279.75 ; C142.2@1214.98,1554.93 v1@1215,1581.44 ; C134.1@1229.12,974.22 v1(1265,974.22) ; Y3.4@1255.64,1247.63 1255.64,1285 1266.82,1296.18 v1(1286.73,1296.18) ; v1(1316.18,963.49) C234.1@1316.18,1025 v1(1316.18,1083.58) ; Y3.2@1318.63,1161.01 1318.63,1126.37 v1(1335,1110)
  other v1: 97.5,1439.98 147.5,1439.98 97.5,1489.98 147.5,1489.98
  other v2: 468.69,975.68 431.29,998.32 506.09,998.32 468.69,1020.96
INT1_PB: Q3.2 R181.1 SW4.2 SW4.4 U34.3 | length 1105.8
  Top Layer w4: v1(630,2155) 638.03,2146.97 U34.3@651.22,2146.97
  Top Layer w5.3: Q3.2@1163.72,2064.27 1163.72,2085.68 1151.5,2097.89 R181.1@1151.5,2146.38 v1(1177.09,2146.38) 1200,2169.29 1200,2216 1236.28,2252.28 SW4.2@1264.76,2252.28 SW4.4@1485.24,2252.28
  SIG 1 w4.75: v1(630,2155) 672.78,2155 719.17,2201.4 827.28,2201.4 862.57,2166.11 1157.36,2166.11 v1(1177.09,2146.38)
LED_A0: R271.2 R274.2 U48.9 | length 166.8
  Top Layer w5.3: R274.2@1954.55,1739.85 R271.2@1954.55,1804.54 1985,1804.54 1994.54,1795 U48.9@2052.72,1795
LED_A1: R270.2 R276.2 U48.10 | length 198.7
  Top Layer w5.3: R276.2@1954.55,1616.57 R270.2@1954.55,1676.88 1954.55,1697.41 2002.14,1745 U48.10@2052.72,1745
LED_A2: R269.2 R275.2 U48.7 | length 157.7
  Top Layer w5.3: U48.7@2267.28,1745 2320,1745 2333.45,1731.55 R269.2@2364.39,1731.55 R275.2@2364.39,1676.55
LED_ANODE0: D7.2 R262.1 | length 60
  Top Layer w5.3: R262.1@2609.29,2239.8 D7.2@2669.29,2239.8
LED_ANODE1: D8.2 R263.1 | length 60
  Top Layer w5.3: R263.1@2469.29,2239.8 D8.2@2529.29,2239.8
LED_ANODE2: D9.2 R264.1 | length 60
  Top Layer w5.3: R264.1@2329.29,2239.8 D9.2@2389.29,2239.8
LED_ANODE3: D10.2 R266.1 | length 60
  Top Layer w5.3: R266.1@2189.29,2239.8 D10.2@2249.29,2239.8
LED_ANODE4: D11.2 R267.1 | length 60
  Top Layer w5.3: R267.1@2017.87,2239.8 D11.2@2077.87,2239.8
LED_ANODE5: D12.2 R273.1 | length 60
  Top Layer w5.3: R273.1@1877.87,2239.8 D12.2@1937.87,2239.8
LED_ANODE6: D13.2 R277.1 | length 60
  Top Layer w5.3: R277.1@1737.87,2239.8 D13.2@1797.87,2239.8
LED_ANODE7: D14.2 R279.1 | length 60
  Top Layer w5.3: R279.1@1617.87,2239.8 D14.2@1677.87,2239.8
LED_DRAIN0: D7.1 U48.3 | length 868.3
  Top Layer w5.3: U48.3@2267.28,1545 2386.68,1545 2503.45,1661.76 2503.45,1885.57 2550,1932.12 2550,2057.52 D7.1@2669.29,2176.81
LED_DRAIN1: D8.1 U48.4 | length 799.1
  Top Layer w5.3: U48.4@2267.28,1595 2414.99,1595 2490,1670.01 2490,1830 2463.14,1856.86 2463.14,2110.66 D8.1@2529.29,2176.81
LED_DRAIN2: D9.1 U48.5 | length 757.1
  Top Layer w5.3: U48.5@2267.28,1645 2444.38,1645 2475,1675.62 2475,1819.57 2448.33,1846.24 2448.33,2117.78 D9.1@2389.29,2176.81
LED_DRAIN3: D10.1 U48.6 | length 532.3
  Top Layer w5.3: D10.1@2249.29,2176.81 2254.1,2172 2254.1,1885 2225,1855.9 2225,1705 2235,1695 U48.6@2267.28,1695
LED_DRAIN4: D11.1 U48.11 | length 1263.5
  Top Layer w5.3: U48.11@2052.72,1695 2006.11,1695 1981.63,1670.52 1981.63,1588.91 1958.52,1565.79 1737.9,1565.79 1724.73,1578.96 1724.73,1825.08 1792.67,1893.02 1905.23,1893.02 1951.2,1938.99 1951.2,2082.06 1991.5,2122.36 2023.42,2122.36 D11.1@2077.87,2176.81
LED_DRAIN5: D12.1 U48.12 | length 1118.8
  Top Layer w5.3: D12.1@1937.87,2176.81 1850.57,2089.51 1850.57,1938.37 1815.83,1903.62 1788.27,1903.62 1713.63,1828.98 1713.63,1575.07 1733.51,1555.19 1962.91,1555.19 1997.72,1590 1997.72,1630.05 2012.67,1645 U48.12@2052.72,1645
LED_DRAIN6: D13.1 U48.13 | length 1026.8
  Top Layer w5.3: D13.1@1797.87,2176.81 1763.14,2142.07 1763.14,1893.48 1703.03,1833.37 1703.03,1570.68 1729.12,1544.59 1967.3,1544.59 2017.71,1595 U48.13@2052.72,1595
LED_DRAIN7: D14.1 U48.14 | length 1007
  Top Layer w5.3: D14.1@1677.87,2176.81 1663.14,2162.07 1663.14,1895.54 1691.94,1866.74 1691.94,1566.78 1724.73,1533.99 1971.69,1533.99 1982.7,1545 U48.14@2052.72,1545
MDIO_CLOCK: U17.10 U22.42 U37.42 | length 3365.5
  SIG 1 w4.75: v1(4904.79,994.9) 4963.87,935.83 5007.97,935.83 5013.01,940.86 5170.43,940.86 5187.78,958.21 5187.78,1177.47 5243.35,1233.04 5472.76,1233.04 5586.94,1347.22 5852.01,1347.22 5979.23,1220 6480.14,1220 v1(6506.28,1193.86) 6550.14,1150 6603.81,1150 6623.81,1170 6623.81,1420.69 6610,1434.5 6610,1565.56 6628.35,1583.91 6628.35,1753.39 6615.77,1765.97 6615.77,1825.59 6615.88,1825.71 6615.88,1832.46 v1(6618.42,1835)
  Bottom Layer w5.3: U17.10@4855.28,1004.38 4895.34,1004.38 v1(4904.79,994.9) ; v1(6506.28,1193.86) 6509.71,1193.86 6514.05,1189.52 6608.82,1189.52 6639.52,1158.82 6639.52,904.83 6615.33,880.64 U22.42@6615.33,853.9 ; U37.42@6615.33,1803.9 6615.33,1831.92 v1(6618.42,1835)
MDIO_DATA: U17.6 U22.41 U37.41 | length 2995
  SIG 1 w4.75: v1(4901.64,1100.33) 4912.39,1089.58 5049.06,1089.58 5078.8,1059.84 5120,1059.84 5155,1094.84 5155,1166.39 5231.71,1243.09 5468.59,1243.09 5582.78,1357.27 5856.17,1357.27 5983.39,1230.05 6500.38,1230.05 6560.43,1170 v1(6578.11,1170) 6613.76,1205.64 6613.76,1369.54 6578.11,1405.18 6578.11,1760.77 v1(6595.65,1778.31)
  Bottom Layer w5.3: U17.6@4855.28,1083.12 4884.43,1083.12 v1(4901.64,1100.33) ; v1(6578.11,1170) 6578.11,1024.27 6609.52,992.86 6609.52,913.29 6599.52,903.29 6599.52,876.91 6595.65,873.04 U22.41@6595.65,853.9 ; v1(6595.65,1778.31) U37.41@6595.65,1803.9
MUX_EN_GPIO58_INV: R96.2 U46.4 U49.15 U51.15 | length 2759.9
  Top Layer w5.3: U51.15@4542.2,1691.89 4578.14,1691.89 4604.13,1665.9 4686.4,1665.9 4703.5,1683 v1(4703.5,1711.5) ; U49.15@5877.2,889.2 5924.04,889.2 v1(5931,882.24) 5946.5,866.74 5946.5,808.04 5958.17,796.38 R96.2@5986.5,796.38 6012.17,770.71 U46.4@6054.41,770.71
  Bottom Layer w5.3: v1(4703.5,1711.5) 4767.5,1775.5 5073.5,1775.5 5203,1905 5790.5,1905 5930,1765.5 5930,1732 5971.25,1690.75 5971.25,1381.75 5983.45,1369.55 5983.45,1019.45 5931,967 v1(5931,882.24)
NetC222_1: C222.1 R246.1 R247.1 | length 238.7
  Top Layer w5.3: v1(6921.84,201.12) 6940,219.27 C222.1@6940,241.38
  SIG 1 w5.3: v1(6921.84,72.38) v1(6921.84,201.12)
  Bottom Layer w5.3: v1(6921.84,72.38) 6922.14,72.09 R246.1@6952.8,72.09 ; v1(6921.84,201.12) 6922.14,200.83 R247.1@6952.8,200.83
NetD2_2: D2.2 R257.1 | length 75.9
  Top Layer w5.3: D2.2@1898.27,970.2 1898.27,949.12 1918.27,929.12 R257.1@1918.27,902.63
NetD3_2: D3.2 R259.1 | length 54.4
  Top Layer w5.3: D3.2@196.5,1531.39 197.88,1530 R259.1@250.32,1530
NetD4_2: D4.2 R313.1 | length 67.3
  Top Layer w5.3: R313.1@2745.47,2243.74 D4.2@2812.72,2243.74
NetD5_1: D5.1 Q13.3 | length 68.9
  Top Layer w5.3: Q13.3@1967.4,123.39 D5.1@2036.27,123.39
NetD5_2: D5.2 R314.1 | length 68
  Top Layer w5.3: D5.2@2036.27,60.4 2101.71,60.4 R314.1@2103.52,62.21
NetD6_2: D6.2 R315.1 | length 55
  Top Layer w5.3: D6.2@2866.5,119.75 2866.75,120 R315.1@2921.38,120
NetDS1_1: DS1.1 Q10.2 | length 98.7
  Top Layer w5.3: DS1.1@2734.5,1992.4 2767.4,1992.4 2793.4,2018.4 Q10.2@2822.41,2018.4
NetDS1_2: DS1.2 R265.1 | length 81.8
  Top Layer w5.3: R265.1@2655.77,1917.12 2655.77,1946.53 2671.5,1962.26 DS1.2@2671.5,1992.4
NetDS2_1: DS2.1 Q11.3 | length 67.7
  Top Layer w5.3: Q11.3@5865.4,2065.27 5891.41,2065.27 5897.32,2059.36 DS2.1@5930.69,2059.36
NetDS2_2: DS2.2 R302.1 | length 70
  Top Layer w5.3: DS2.2@5930.69,2122.36 5998.4,2122.36 R302.1@6000,2123.95
NetDS3_2: DS3.2 R260.1 | length 64.8
  Top Layer w5.3: DS3.2@196.5,1614.41 210.91,1600 R260.1@255.32,1600
NetL4_1: L4.1 U36.9 | length 18.6
  Top Layer w12: U36.9@2858.62,307.34 2877.25,307.34
NetQ10_1: Q10.1 R272.2 | length 131.2
  Top Layer w5.3: Q10.1@2873.59,2018.4 2891.6,2018.4 2935.31,1974.69 R272.2@2935.31,1923.35
NetQ11_1: Q11.1 R303.2 | length 55.9
  Top Layer w5.3: R303.2@5734.69,2090.86 Q11.1@5790.6,2090.86
NetQ13_1: Q13.1 R317.2 | length 69
  Top Layer w5.3: R317.2@1839.67,127.49 1839.67,139.67 1848.98,148.98 Q13.1@1892.6,148.98
NetR8_2: R8.2 U4.4 U4.5 | length 145.4
  Bottom Layer w5.3: R8.2@3586.76,109.77 3586.45,110.09 3586.45,158.78 3591.82,164.16 U4.5@3618.83,164.16 3618.83,146.31 3627.93,137.2 3637.86,137.2 3642.45,141.79 U4.4@3642.45,156.28
NetR22_2: R22.2 SW1.1 | length 84.4
  Top Layer w12: SW1.1@3812.01,119.51 R22.2@3896.38,119.51
NetR23_2: R23.2 SW1.2 | length 84.4
  Top Layer w12: SW1.2@3812.01,169.51 R23.2@3896.38,169.51
NetR24_2: R24.2 SW1.3 | length 84.4
  Top Layer w12: SW1.3@3812.01,219.51 R24.2@3896.38,219.51
NetR25_2: R25.2 SW1.4 | length 84.4
  Top Layer w12: SW1.4@3812.01,269.51 R25.2@3896.38,269.51
NetR245_2: R245.2 U42.1 | length 77.9
  Bottom Layer w5.3: U42.1@7127.91,174.84 7145.98,174.84 7155,183.86 7155,201.46 7165,211.46 R245.2@7180.31,211.46
NetR249_2: R249.2 U42.4 | length 81.8
  Bottom Layer w5.3: U42.4@7127.91,98.07 7147.67,98.07 7153.38,92.36 7153.38,68.08 7160,61.46 R249.2@7180.31,61.46
NetR256_2: R256.2 U52.18 U52.19 U52.20 U52.21 | length 504.7
  Top Layer w5.3: U52.21@4535.47,843.23 4535.47,885.47 4545.28,895.28 4565,895.28 ; U52.20@4555.16,843.23 4555.16,885.44 4565,895.28 ; U52.19@4574.84,843.23 4574.84,888.3 4581.82,895.28 ; U52.18@4594.53,843.23 4594.53,895.28 ; R256.2@4816.77,861.65 4783.14,895.28 4594.53,895.28 ; 4565,895.28 4581.82,895.28 ; 4581.82,895.28 4594.53,895.28
NetU10_4: U10.4 U11.5 | length 141.4
  Top Layer w5.3: U10.4@321.92,594.53 357.03,594.53 382.5,620 U11.5@452.76,620
PG_VDD_1V2: R295.1 R317.1 U2.3 U29.5 | length 2468.2
  Top Layer w5.3: v1(1771.58,127.81) 1771.9,127.49 R317.1@1800.3,127.49 ; U2.3@1967.11,1242.05 1967.11,1164.31 R295.1@1966.38,1163.59 1966.38,1140 1978.86,1127.52 v1(2055,1127.52)
  Top Layer w10: v1(2413.01,960) 2421.49,951.52 U29.5@2441.44,951.52
  SIG 1 w5.3: v1(1771.58,127.81) 1577.19,127.81 1549.15,155.85 1549.15,353 1796.14,600 1945.01,600 1980.18,635.16 1980.18,838.97 1907.54,911.6 1907.54,952.75 1928.97,974.18 2016.04,974.18 2040.84,998.98 2040.84,1026.01 2024.39,1042.47 2024.39,1096.91 v1(2055,1127.52) 2117,1189.52 2363.09,1189.52 2413.01,1139.6 v1(2413.01,960)
PG_VSYS_3V3: R296.1 U2.6 U32.5 | length 1032.4
  Top Layer w5.3: U2.6@2075.37,1316.85 2103.52,1316.85 2120.87,1334.19 2120.87,1350.49 2135.38,1365 R296.1@2152.79,1365 2152.79,1344.27 2187.27,1309.78 2431.62,1309.78 2490,1368.16 v1(2490,1484.99)
  Top Layer w10: v1(2774.69,1592.62) 2783.16,1584.14 U32.5@2803.11,1584.14
  SIG 1 w4.75: v1(2490,1484.99) 2490,1572.16 2510.46,1592.62 v1(2774.69,1592.62)
PORZ_DELAY: U5.2 U6.4 | length 86.3
  Top Layer w5.3: U6.4@2064.38,777.98 2064.38,805.35 2081.31,822.28 U5.2@2081.31,857.27
PORZ_PB: Q1.2 R177.1 SW2.2 SW2.4 U34.1 | length 950.9
  Top Layer w4: U34.1@678.78,2146.97 691.97,2146.97 v1(700,2155)
  Top Layer w5.3: SW2.2@367.32,2252.28 SW2.4@587.8,2252.28 660.7,2252.28 700,2212.98 v1(700,2155)
  SIG 1 w5.3: v1(700,2155) 804.83,2155 969.83,1990 v1(1000,1990)
  Bottom Layer w5.3: Q1.2@890.38,1955 924.75,1955 932.5,1947.24 R177.1@966.87,1947.24 992.2,1947.24 1000,1955.04 v1(1000,1990)
PR0_PRU0_GPIO0: U1.K17 U23.2 | length 1520
  Top Layer w4: U1.K17@4051.07,1099.33 4068.69,1081.71 4100.24,1081.71
  Top Layer w5.3: 4100.24,1081.71 4265.13,1081.71 4278.52,1095.1 4382.53,1095.1 4394.52,1107.1 4463.61,1107.1 4506.05,1149.54 4738.98,1149.54 4772.52,1116 4843.09,1116 v1(4854.47,1127.38) ; v1(4670.59,1574.61) 4690.28,1594.29 U23.2@4762.24,1594.29
  Bottom Layer w5.3: v1(4670.59,1574.61) 4690.11,1555.09 4757.29,1555.09 4776.23,1536.14 4776.23,1334.57 4837.59,1273.22 4837.59,1221.91 4854.47,1205.03 v1(4854.47,1127.38)
PR0_PRU0_GPIO0_MUX: J2/J4.33 U23.42 | length 2981.7
  Top Layer w5.3: U23.42@4797.68,1629.73 v1(4797.68,1689)
  SIG 1 w4.75: J2/J4.33@2304.17,1950 2363.41,2009.24 2521.06,2009.24 2531.17,2019.35 2655.89,2019.35 2663.61,2027.07 2990.71,2027.07 3033.3,1984.48 3246.07,1984.48 3328.44,2066.84 3328.44,2077.33 3437.45,2186.34 4325.47,2186.34 4444.93,2066.88 4444.93,1924.26 4470,1899.19 4587.49,1899.19 v1(4797.68,1689)
PR0_PRU0_GPIO1: U1.K18 U23.3 | length 1516.1
  Top Layer w5.3: U1.K18@4082.57,1099.33 4265.76,1099.33 4272.13,1105.7 4378.14,1105.7 4390.13,1117.7 4459.22,1117.7 4501.66,1160.14 4748.73,1160.14 4764.08,1175.48 4865.69,1175.48 v1(4883.93,1157.24) ; v1(4720.59,1574.61) U23.3@4762.24,1574.61
  Bottom Layer w5.3: v1(4720.59,1574.61) 4742.56,1596.58 4761.04,1615.05 4848.61,1615.05 4904.17,1559.5 4904.17,1177.49 v1(4883.93,1157.24)
PR0_PRU0_GPIO1_MUX: J2/J4.32 U23.40 | length 2971.9
  Top Layer w5.3: U23.40@4837.05,1629.73 4837.05,1666.14 v1(4860.91,1690)
  SIG 1 w4.75: J2/J4.32@2404.17,1950 2453.36,1999.19 2570.8,1999.19 2580.91,2009.3 2698.35,2009.3 2704.05,2015 2988.57,2015 3029.14,1974.43 3250.24,1974.43 3338.49,2062.68 3338.49,2073.17 3441.61,2176.29 4263.19,2176.29 4355.61,2083.87 4355.61,1928.53 4395,1889.14 4563.86,1889.14 4786,1667 4837.91,1667 v1(4860.91,1690)
PR0_PRU0_GPIO2: U1.J18 U23.4 | length 1516.1
  Top Layer w5.3: U1.J18@4082.57,1130.83 4086.86,1126.53 4257.41,1126.53 4260.4,1129.53 4371.98,1129.53 4381.35,1138.9 4450.44,1138.9 4494.22,1182.68 4722.08,1182.68 v1(4731.01,1191.61) ; v1(4670.59,1535.24) 4690.28,1554.92 U23.4@4762.24,1554.92
  Bottom Layer w5.3: v1(4670.59,1535.24) 4692.98,1535.24 4712.83,1515.39 4728.68,1515.39 4755,1489.07 4755,1323.69 4702.53,1271.22 4667.23,1271.22 4653.64,1284.8 4597.68,1284.8 4580.99,1268.11 4580.99,1251.6 4591.64,1240.95 4708.91,1240.95 4724.45,1256.5 4737.65,1256.5 4750,1244.15 4750,1230.84 4731.01,1211.85 v1(4731.01,1191.61)
PR0_PRU0_GPIO2_MUX: J2/J4.31 U23.37 | length 2924.8
  Top Layer w5.3: U23.37@4892.17,1594.29 v1(4933.82,1594.29)
  SIG 1 w4.75: J2/J4.31@2504.17,1950 2547.61,1950 2596.85,1999.25 2863.55,1999.25 2898.42,1964.38 3255.16,1964.38 3348.54,2057.75 3348.54,2069 3445.78,2166.24 4259.03,2166.24 4345.27,2080 4345.27,1923.82 4390,1879.09 4502.91,1879.09 4699.99,1682.01 4733.4,1682.01 4780.53,1634.88 4893.23,1634.88 v1(4933.82,1594.29)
